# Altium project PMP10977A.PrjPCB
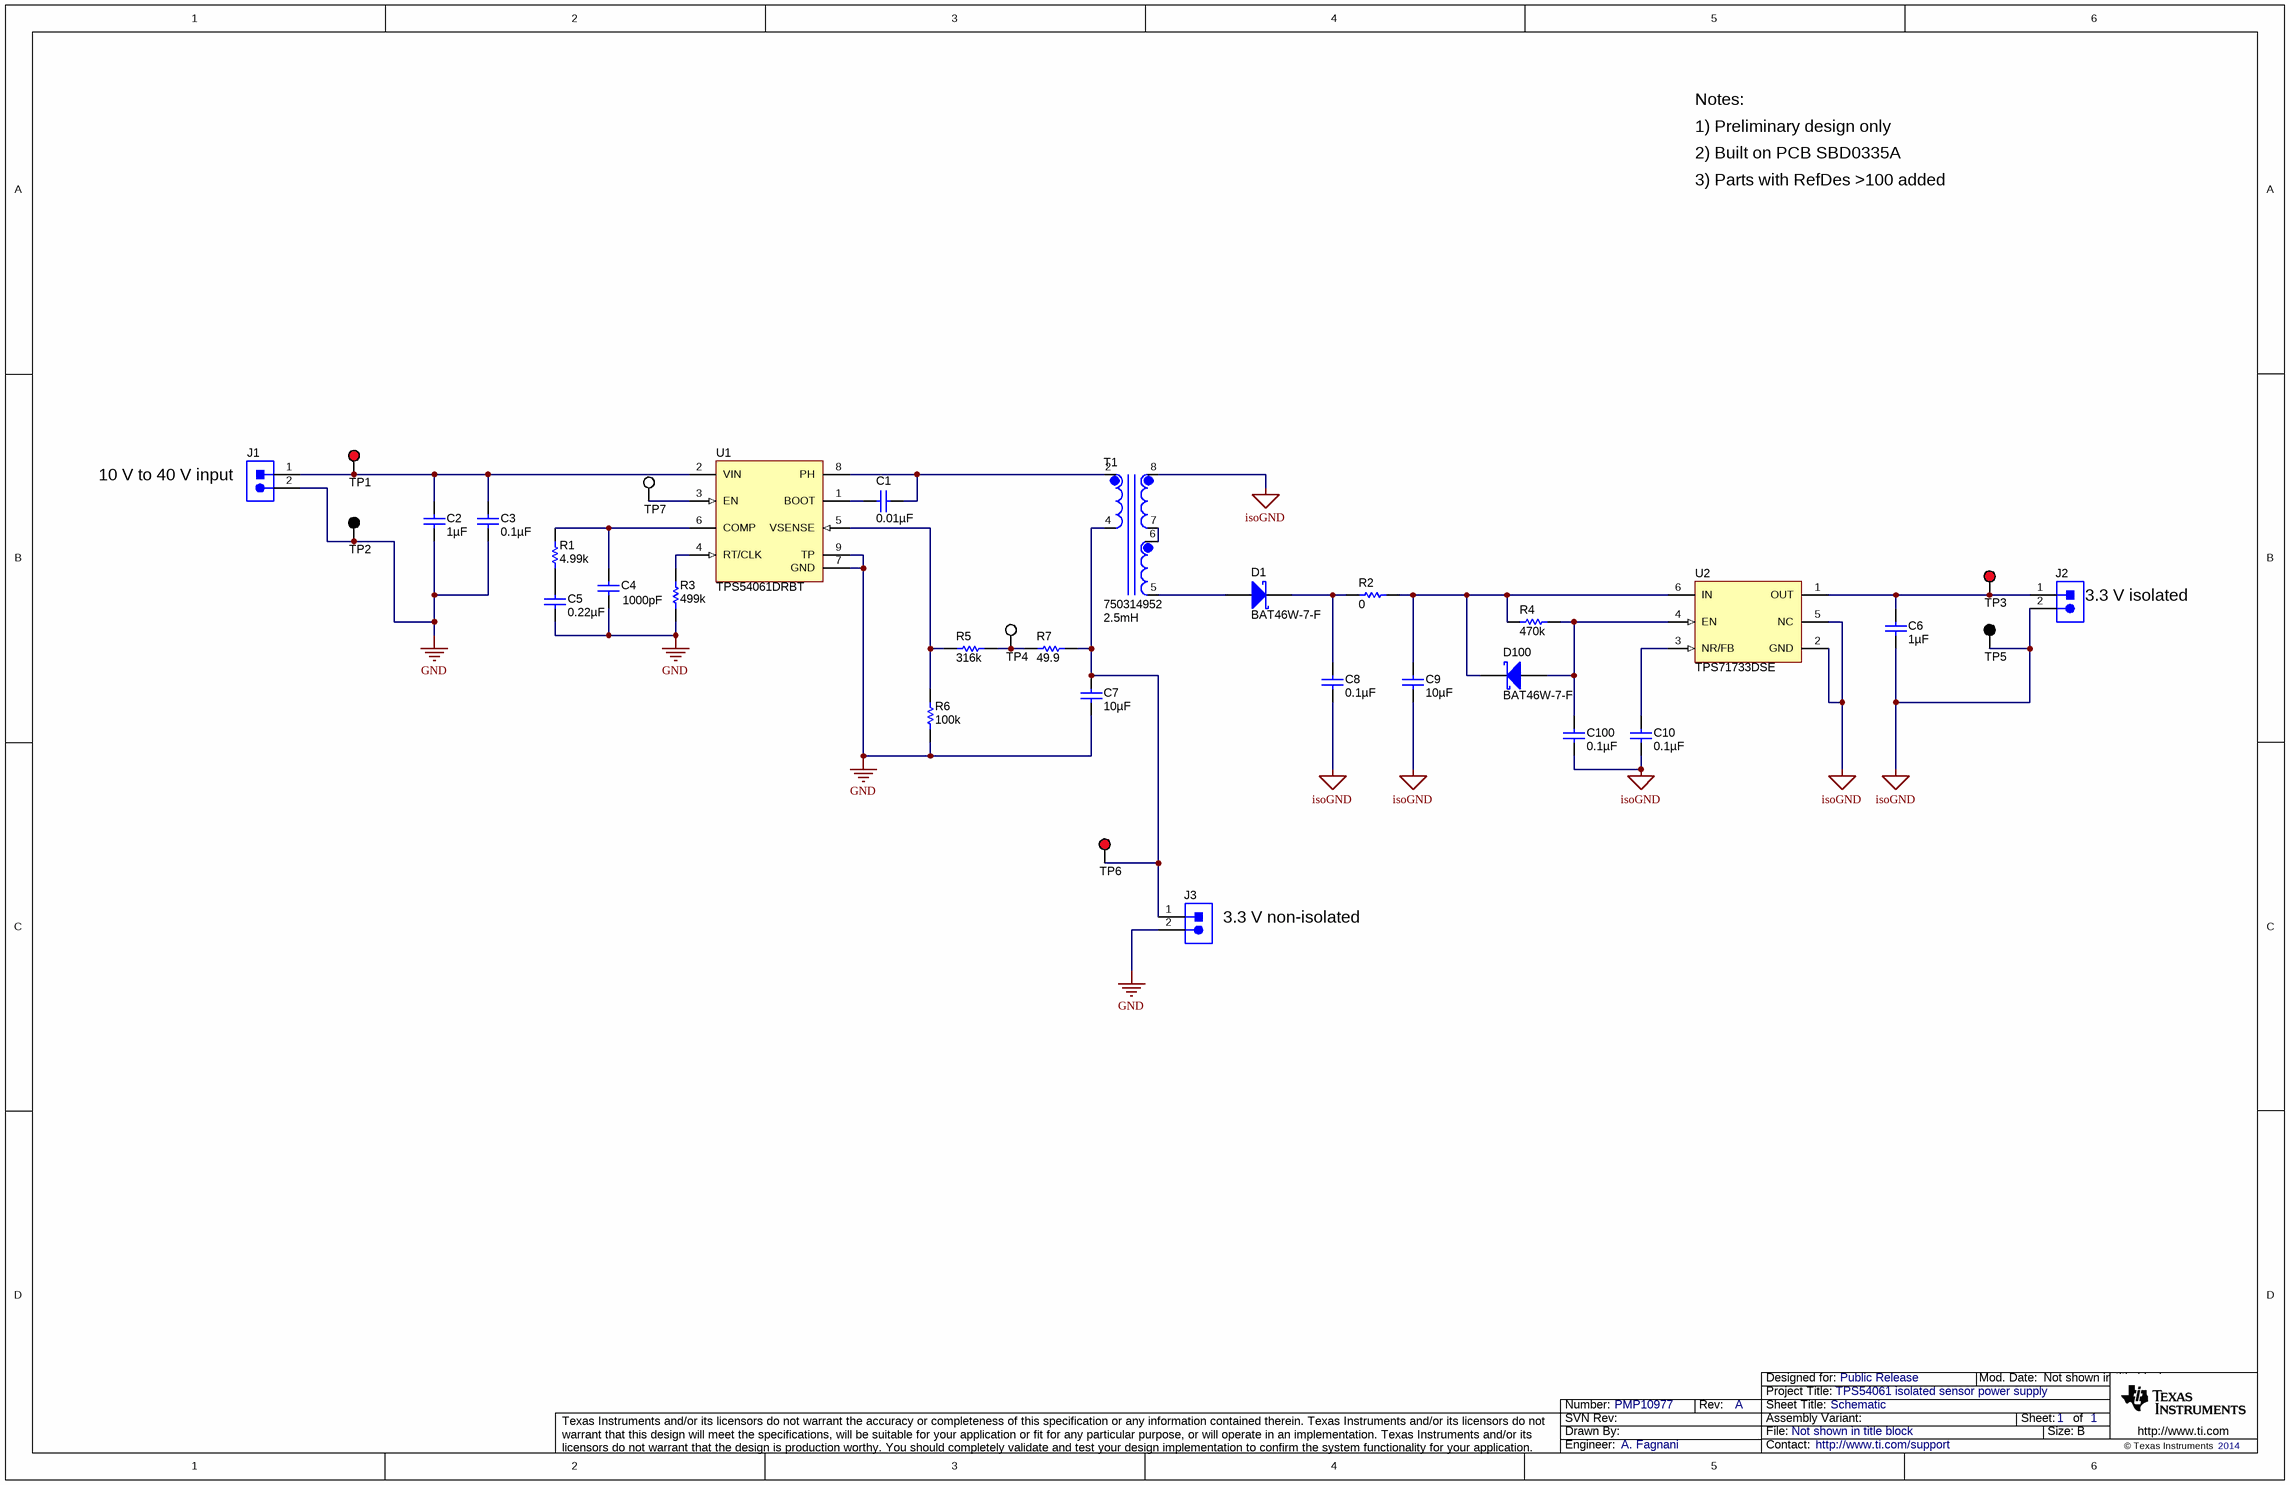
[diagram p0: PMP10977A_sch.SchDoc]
CopyrightYear: 2014; PCB_Layout: A. Fagnani; PCB_Rev: A; PRJ_Customer: Public Release; PRJ_Engineer: A. Fagnani; PRJ_Number: PMP10977; PRJ_Title: TPS54061 isolated sensor power supply; SCH_Rev: A; TechSupport: http://www.ti.com/support
2 sheets, 39 parts. Net scope: global (net labels, ports and power ports of the same name join across sheets).
Sheets:
  PMP10977A_sch.SchDoc
  PMP10977A_hdw.SchDoc

## Sheet PMP10977A_sch.SchDoc: Schematic
size 431 x 279 mm; Date: Not shown in title block; ApprovedBy: Not shown in title block; CheckedBy: Not shown in title block; Author: Not shown in title block; CompanyName: Not shown in title block; Engineer: Not shown in title block; Organization: Not shown in title block; Address1: Not shown in title block; Address2: Not shown in title block; Address3: Not shown in title block; Address4: Not shown in title block; DocumentNumber: 1; Revision: Use project parameter SCH_Rev; SheetNumber: 1; SheetTotal: 1; PageSetup: Record=PageOptions¦CenterHorizontal=True¦CenterVertical=True¦PrintScale=1.00¦XCorrection=1.00¦YCorrection=1.00¦PrintKind=0¦BorderSize=5000000¦LeftOffset=0¦BottomOffset=0¦Orientation=2¦PaperLength=1000¦PaperWidth=1000¦Scale=100¦PaperSource=15¦PrintQuality=600¦MediaType=1¦DitherType=10¦PaperKind=Letter¦PrintScaleMode=1

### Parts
C1  ValueDisplayed: 0.01µF  [0603]  (hidden comment: GRM188R71C103KA01D)
C2  ValueDisplayed: 1µF  [1206]  (hidden comment: GRM31CR72A105KA01L)
C3  ValueDisplayed: 0.1µF  [0603]  (hidden comment: GRM188R72A104KA35D)
C4  ValueDisplayed: 1000pF  [0603]  (hidden comment: GRM1885C1E102JA01D)
C5  ValueDisplayed: 0.22µF  [0603]  (hidden comment: GRM188R61A224KA01D)
C6  ValueDisplayed: 1µF  [0603]  (hidden comment: GRM188R71A105KA61D)
C7  ValueDisplayed: 10µF  [0805_HV]  (hidden comment: GRM21BR71A106KE51L)
C8  ValueDisplayed: 0.1µF  [0603]  (hidden comment: GCM188R71H104KA57D)
C9  ValueDisplayed: 10µF  [0805_HV]  (hidden comment: GRM21BR71A106KE51L)
C10  ValueDisplayed: 0.1µF  [0603]  (hidden comment: GRM188R70J104KA01D)
C100  ValueDisplayed: 0.1µF  [0603]  (hidden comment: GRM188R70J104KA01D)
D1  BAT46W-7-F  [SOD-123]
D100  BAT46W-7-F  [SOD-123]
J1  800-10-002-10-001000  [Mill-Max_800-10-002-10-001000]  (value not drawn)
J2  800-10-002-10-001000  [Mill-Max_800-10-002-10-001000]  (value not drawn)
J3  800-10-002-10-001000  [Mill-Max_800-10-002-10-001000]  (value not drawn)
R1  ValueDisplayed: 4.99k  [0603]  (hidden comment: CRCW06034K99FKEA)
R2  value 0  [0603]  (hidden comment: CRCW06030000Z0EA)
R3  ValueDisplayed: 499k  [0603]  (hidden comment: CRCW0603499KFKEA)
R4  ValueDisplayed: 470k  [0603]  (hidden comment: CRCW0603470KJNEA)
R5  value 316k  [0603]  (hidden comment: CRCW0603316KFKEA)
R6  value 100k  [0603]  (hidden comment: CRCW0603100KFKEA)
R7  value 49.9  [0603]  (hidden comment: CRCW060349R9FKEA)
T1  750314952  value 2.5mH  [Wurth_750314445]
TP1  5000  [Keystone5000]  (value not drawn)
TP2  5001  [Keystone5001]  (value not drawn)
TP3  5000  [Keystone5000]  (value not drawn)
TP4  5002  [Keystone5002]  (value not drawn)
TP5  5001  [Keystone5001]  (value not drawn)
TP6  5000  [Keystone5000]  (value not drawn)
TP7  5002  [Keystone5002]  (value not drawn)
U1  TPS54061DRBT  [DRB0008B]
U2  TPS71733DSE  [DSE0006A]

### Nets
GND: C2.2 C3.2 C4.2 C5.2 C7.2 J1.2 J3.2 R3.1 R6.1 TP2.1 U1.7(GND) U1.9(TP)
isoGND: C6.2 C8.2 C9.2 C10.2 C100.2 J2.2 T1.8 TP5.1 U2.2(GND) U2.5(NC)
NetC1_1: C1.1 T1.2 U1.8(PH)
NetC1_2: C1.2 U1.1(BOOT)
NetC2_1: C2.1 C3.1 J1.1 TP1.1 U1.2(VIN)
NetC4_1: C4.1 R1.2 U1.6(COMP)
NetC5_1: C5.1 R1.1
NetC6_1: C6.1 J2.1 TP3.1 U2.1(OUT)
NetC7_1: C7.1 J3.1 R7.1 T1.4 TP6.1
NetC8_1: C8.1 D1.1(K) R2.2
NetC9_1: C9.1 D100.1(K) R2.1 R4.2 U2.6(IN)
NetC10_1: C10.1 U2.3(NR/FB)
NetC100_1: C100.1 D100.2(A) R4.1 U2.4(EN)
NetD1_2: D1.2(A) T1.5
NetR3_2: R3.2 U1.4(RT/CLK)
NetR5_1: R5.1 R7.2 TP4.1
NetR5_2: R5.2 R6.2 U1.5(VSENSE)
NetT1_6: T1.6 T1.7
NetTP7_1: TP7.1 U1.3(EN)

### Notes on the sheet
- Notes:
- 1) Preliminary design only
- 2) Built on PCB SBD0335A
- 3) Parts with RefDes >100 added
- (near J1) 10 V to 40 V input
- (near J2) 3.3 V isolated
- (near J3) 3.3 V non-isolated

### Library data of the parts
C1 = GRM188R71C103KA01D: CAP, CERM, 0.01uF, 16V, +/-10%, X7R, 0603; Manufacturer: MuRata; Polarized: N; CompType: Capacitor; U/M: EA; Cap_F: 0.00000001; Tolerance_%: 10; Value1: Unknown; VDC_V: 16; TaMin_C: -55; TaMax_C: 125
C2 = GRM31CR72A105KA01L: CAP, CERM, 1uF, 100V, +/-10%, X7R, 1206; Manufacturer: MuRata; Polarized: N; CompType: Capacitor; U/M: EA; Cap_F: 0.000001; Tolerance_%: 10; Value1: Unknown; VDC_V: 100; TaMin_C: -55; TaMax_C: 125; Cap_Case: 2220
C3 = GRM188R72A104KA35D: CAP, CERM, 0.1uF, 100V, +/-10%, X7R, 0603; Manufacturer: MuRata; Polarized: N; CompType: Capacitor; U/M: EA; Cap_F: 0.0000001; Tolerance_%: 10; Value1: Unknown; VDC_V: 100; TaMin_C: -55; TaMax_C: 125
C4 = GRM1885C1E102JA01D: CAP, CERM, 1000pF, 25V, +/-5%, C0G/NP0, 0603; Manufacturer: MuRata; Polarized: N; CompType: Capacitor; U/M: EA; Cap_F: 0.000000001; Tolerance_%: 5; Value1: Unknown; VDC_V: 25; TaMin_C: -55; TaMax_C: 125
C5 = GRM188R61A224KA01D: CAP, CERM, 0.22 µF, 10 V, +/- 10%, X5R, 0603; Manufacturer: MuRata; Polarized: N; CompType: Capacitor; Value: 0.22uF; U/M: EA; Cap_F: 0.00000022; Tolerance_%: 10; Value1: Unknown; Value2: 10V; TaMin_C: -55; TaMax_C: 85
C6 = GRM188R71A105KA61D: CAP, CERM, 1uF, 10V, +/-10%, X7R, 0603; Manufacturer: MuRata; Polarized: N; CompType: Capacitor; U/M: EA; Cap_F: 0.000001; Tolerance_%: 10; ESR_Ohm: 0.011; Value1: 0.011 ohm; TaMin_C: -55; TaMax_C: 125
C7 C9 = GRM21BR71A106KE51L: CAP, CERM, 10 µF, 10 V, +/- 10%, X7R, 0805; Manufacturer: MuRata; Polarized: N; CompType: Capacitor; Value: 10uF; U/M: EA; Cap_F: 0.00001; Tolerance_%: 10; ESR_ohm: 0.003; Value1: 0.003 ohm; Value2: 10V; TaMin_C: -55; TaMax_C: 125; Cap_Case: 0805
C8 = GCM188R71H104KA57D: CAP, CERM, 0.1 µF, 50 V, +/- 10%, X7R, 0603; Manufacturer: MuRata; Polarized: N; CompType: Capacitor; Value: 0.1uF; U/M: EA; Cap_F: 0.0000001; Tolerance_%: 10; ESR_ohm: 0.02; Value1: 0.02 ohm; VDC_V: 50; Value2: 50V; IRMS_A: 1.84; TaMin_C: -55; TaMax_C: 125
C10 C100 = GRM188R70J104KA01D: CAP, CERM, 0.1uF, 6.3V, +/-10%, X7R, 0603; Manufacturer: MuRata; Polarized: N; CompType: Capacitor; U/M: EA; Cap_F: 0.0000001; Tolerance_%: 10; Value1: Unknown; VDC_V: 6.3; TaMin_C: -55; TaMax_C: 125
D1 D100 = BAT46W-7-F: Diode, Schottky, 100 V, 0.15 A, SOD-123; Manufacturer: Diodes Inc.; U/M: EA; Vf_V: 0.6; Value: 100V; Value1: 0.15A; Value2: 0.6V; Io_A: 0.15; Vr_V: 100
J1-J3 = 800-10-002-10-001000: Header, 2x1, 100mil, SMT; Manufacturer: Mill-Max; SymbolCreator: a0412235; U/M: EA
R1 = CRCW06034K99FKEA: RES, 4.99 k, 1%, 0.1 W, 0603; Manufacturer: Vishay-Dale; CompType: Resistor; Value: 4.99k; Res_ohm: 4990; Value_Code: 4k99; Tolerance_%: 1; Power_W: 0.1; Value2: 0.1W; VDC_V: 75; TempCo: 100 ppm/C; EIA_Code: E96; U/M: EA
R2 = CRCW06030000Z0EA: RES, 0 ohm, 5%, 0.1W, 0603; Manufacturer: Vishay-Dale; CompType: Resistor; Value_Code: 0000; Tolerance_%: 5; Power_W: 0.1; VDC_V: 75; TempCo: 200 ppm/C; EIA_Code: E24; U/M: EA
R3 = CRCW0603499KFKEA: RES, 499 k, 1%, 0.1 W, 0603; Manufacturer: Vishay-Dale; CompType: Resistor; Value: 499k; Res_ohm: 499000; Tolerance_%: 1; Power_W: 0.1; Value2: 0.1W; VDC_V: 75; TempCo: 100 ppm/C; EIA_Code: E96; U/M: EA
R4 = CRCW0603470KJNEA: RES, 470 k, 5%, 0.1 W, 0603; Manufacturer: Vishay-Dale; CompType: Resistor; Value: 470k; Res_ohm: 470000; Tolerance_%: 5; Power_W: 0.1; Value2: 0.1W; VDC_V: 75; TempCo: 200 ppm/C; EIA_Code: E24; U/M: EA
R5 = CRCW0603316KFKEA: RES, 316k ohm, 1%, 0.1W, 0603; Manufacturer: Vishay-Dale; CompType: Resistor; Res_ohm: 316000; Tolerance_%: 1; Power_W: 0.1; VDC_V: 75; TempCo: 100 ppm/C; EIA_Code: E96; U/M: EA
R6 = CRCW0603100KFKEA: RES, 100k ohm, 1%, 0.1W, 0603; Manufacturer: Vishay-Dale; CompType: Resistor; Res_ohm: 100000; Tolerance_%: 1; Power_W: 0.1; VDC_V: 75; TempCo: 100 ppm/C; EIA_Code: E96; U/M: EA
R7 = CRCW060349R9FKEA: RES, 49.9 ohm, 1%, 0.1W, 0603; Manufacturer: Vishay-Dale; CompType: Resistor; Value_Code: 49R9; Tolerance_%: 1; Power_W: 0.1; VDC_V: 75; TempCo: 100 ppm/C; EIA_Code: E96; U/M: EA
T1 = XFMR_750311880: Transformer, ±10%; Manufacturer: WE; Area: 172200
TP1 TP3 TP6 = 5000: Test Point, Miniature, Red, TH; Manufacturer: Keystone; CompType: Test Point Loop; U/M: EA
TP2 TP5 = 5001: Test Point, Miniature, Black, TH; Manufacturer: Keystone; CompType: Test Point Loop; U/M: EA
TP4 TP7 = 5002: Test Point, Miniature, White, TH; Manufacturer: Keystone; CompType: Test Point Loop; U/M: EA
U1 = TPS54062DRBT: Buck Step Down Regulator with 4.7 to 60 V Input and 0.8 to 58 V Output, -40 to 125 degC, 8-Pin SON (DRB), Green (RoHS & no Sb/Br); Manufacturer: Texas Instruments; Alternate Manufacturer: None; Alternate PartNumber: Equivalent; Duty Cycle(Max)(%): 98; Iout(Max)(A): 0.2; Iq(Typ)(mA): 0.089; Rating: Catalog; Regulated Outputs(#): 1; SubFamily: Step-Down Regulator; Switch Current Limit(Typ)(A): 0.13; Synchronous Rectification: TRUE; Vin(Max)(V): 60; Vin(Min)(V): 4.7; Vout(Max)(V): 58; Vout(Min)(V): 0.8
U2 = TPS71733DSE: Low Noise, High-Bandwidth PSRR Low-Dropout 150mA Linear Regulator, DSE0006A; Alternate Manufacturer: None; Manufacturer: Texas Instruments; SymbolCreator: a0411947; CompType: IC; U/M: EA

## Sheet PMP10977A_hdw.SchDoc: Other
size 431 x 279 mm; Date: Not shown in title block; ApprovedBy: Not shown in title block; CheckedBy: Not shown in title block; Author: Not shown in title block; CompanyName: Not shown in title block; Engineer: Not shown in title block; Organization: Not shown in title block; Address1: Not shown in title block; Address2: Not shown in title block; Address3: Not shown in title block; Address4: Not shown in title block; DocumentNumber: 1; Revision: Use project parameter SCH_Rev; SheetNumber: 1; SheetTotal: 1; PageSetup: Record=PageOptions¦CenterHorizontal=True¦CenterVertical=True¦PrintScale=1.00¦XCorrection=1.00¦YCorrection=1.00¦PrintKind=0¦BorderSize=5000000¦LeftOffset=0¦BottomOffset=0¦Orientation=2¦PaperLength=1000¦PaperWidth=1000¦Scale=100¦PaperSource=15¦PrintQuality=600¦MediaType=1¦DitherType=10¦PaperKind=Letter¦PrintScaleMode=1
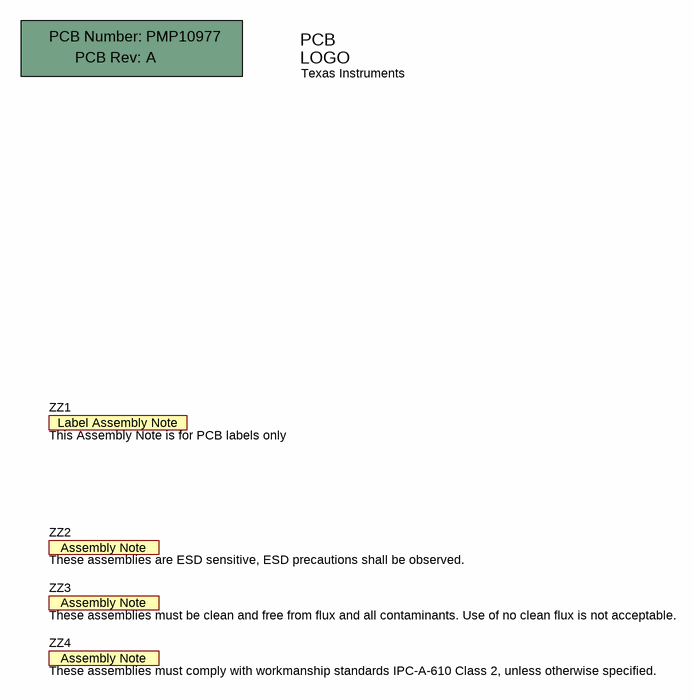
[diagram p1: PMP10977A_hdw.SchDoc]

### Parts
!PCB1  Printed Circuit Board  (value not drawn)  (mechanical)
Logo1  Texas Instruments  [TI_Symbol_Overlay_Small]  (no BOM)
ZZ1  This Assembly Note is for PCB labels only  [AssemblyNoteLabel]  (no BOM)
ZZ2  These assemblies are ESD sensitive, ESD precautions shall be observed.  [AssemblyNote]  (no BOM)
ZZ3  These assemblies must be clean and free from flux and all contaminants. Use of no clean flux is not acceptable.  [AssemblyNote]  (no BOM)
ZZ4  These assemblies must comply with workmanship standards IPC-A-610 Class 2, unless otherwise specified.  [AssemblyNote]  (no BOM)

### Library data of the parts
!PCB1 = PCB: Manufacturer: Any; PartNumber: PMP10977; SymbolCreator: a0412235
Logo1 = TI_Logo: Texas Instrument Corporate Signature; SymbolCreator: codlsc
ZZ1 = AssemblyNoteLabel: SymbolCreator: a0412235
ZZ2-ZZ4 = AssemblyNote: SymbolCreator: codlsc

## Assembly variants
001: not fitted FID1 FID2 FID3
